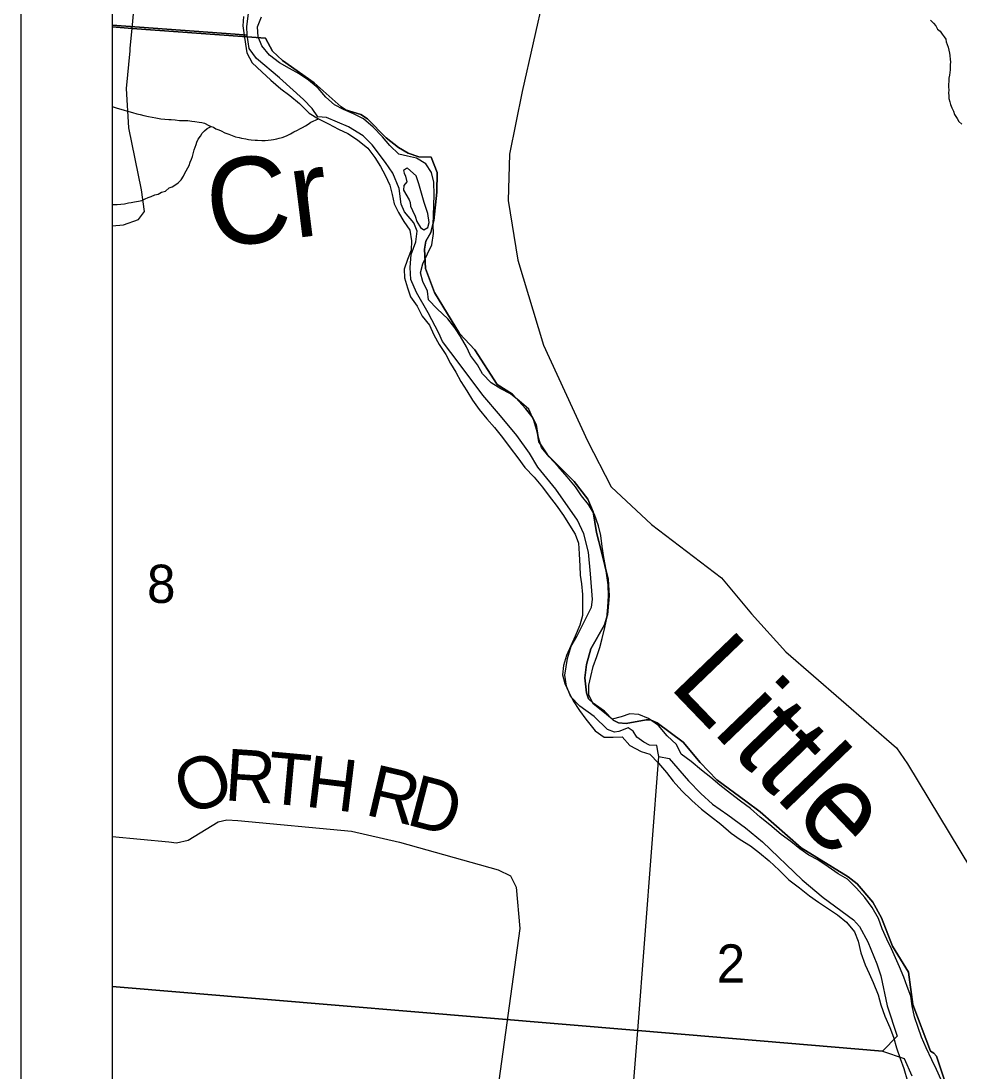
# Model space of a CAD drawing. Extents: x 0.4 to 34.4, y -2.1 to 19.9.
# Drawn here: x 2.9 to 3.928, y 16.79 to 17.94 of the extents above; entities that cross this region are included whole.
import ezdxf

# ---------------------------------------------------------------- set-up
doc = ezdxf.new("R2010")
doc.units = 0
for name, color, linetype in [('GM_X_County', 7, 'Continuous'), ('GM_X_County_Road', 7, 'Continuous'), ('GM_X_Major_River', 7, 'Continuous'), ('GM_X_Major_River_Text', 7, 'Continuous'), ('GM_X_Minor_River', 7, 'Continuous'), ('GM_X_Minor_River_Text', 7, 'Continuous'), ('GM_X_Section', 7, 'Continuous'), ('GM_X_Section_Text', 7, 'Continuous'), ('GM_X_Township', 7, 'Continuous'), ('GM_X_Township_Road', 7, 'Continuous'), ('GM_X_Township_Road_Text', 7, 'Continuous'), ('SH_Data', 7, 'Continuous')]:
    doc.layers.add(name, color=color, linetype=linetype)

msp = doc.modelspace()

# ---------------------------------------------------------------- linework, layer by layer
at = {"layer": 'GM_X_County'}
msp.add_lwpolyline([(9.8001, 15.3423), (9.8001, 18.8357), (3.0001, 18.8357), (3.0001, 12.0357), (9.5074, 12.0357)], dxfattribs=at)
at = {"layer": 'GM_X_County_Road'}
msp.add_lwpolyline([(3.497, 18.0767), (3.4489, 17.8633), (3.4351, 17.7944), (3.4337, 17.7439), (3.4443, 17.6785), (3.4724, 17.5852), (3.5204, 17.4806), (3.5463, 17.4302), (3.5906, 17.3891), (3.6672, 17.3305), (3.7001, 17.291), (3.7375, 17.2495), (3.8587, 17.1441), (3.871, 17.1268), (3.9398, 17.0125), (3.9755, 16.9529), (3.9928, 16.9155), (3.999, 16.8657), (3.9982, 16.7985), (4.0079, 16.7195)], dxfattribs=at)
at = {"layer": 'GM_X_Major_River'}
for points in [[(3.1437, 17.9452), (3.1432, 17.935), (3.1445, 17.9251), (3.1459, 17.9149), (3.1473, 17.9054), (3.1532, 17.8946), (3.164, 17.8846), (3.1737, 17.8757), (3.1846, 17.8661), (3.1944, 17.8587), (3.2052, 17.8499), (3.2157, 17.8394), (3.2258, 17.8332), (3.2368, 17.8277), (3.2477, 17.8219), (3.2579, 17.8172), (3.2687, 17.8102), (3.28, 17.8013), (3.2874, 17.7909), (3.2937, 17.781), (3.2989, 17.7714), (3.304, 17.7607), (3.3065, 17.7504), (3.3087, 17.7402), (3.3134, 17.7306), (3.3194, 17.721), (3.326, 17.7115), (3.3278, 17.6997), (3.3272, 17.6895), (3.3233, 17.6793), (3.3197, 17.6687), (3.3199, 17.6592), (3.3235, 17.6482), (3.3268, 17.6383), (3.3339, 17.6279), (3.3394, 17.6172), (3.3476, 17.6072), (3.3523, 17.5965), (3.3579, 17.5862), (3.3653, 17.5751), (3.3705, 17.5652), (3.3764, 17.5556), (3.3819, 17.5456), (3.3882, 17.5353), (3.3945, 17.525), (3.4019, 17.515), (3.4101, 17.5046), (3.4187, 17.495), (3.4273, 17.4843), (3.4358, 17.4728), (3.444, 17.462), (3.4518, 17.4513), (3.4619, 17.4409), (3.4712, 17.4297), (3.4786, 17.4201), (3.4861, 17.4102), (3.4943, 17.3987), (3.5009, 17.3883), (3.5068, 17.3784), (3.5105, 17.3685), (3.5114, 17.3567), (3.512, 17.3434), (3.5126, 17.3335), (3.514, 17.324), (3.5149, 17.3123), (3.5151, 17.3013), (3.5149, 17.2891), (3.5121, 17.2786), (3.507, 17.2665), (3.5023, 17.256), (3.4976, 17.2454), (3.494, 17.2345), (3.4931, 17.2243), (3.4956, 17.2147), (3.5, 17.2052), (3.5048, 17.1956), (3.5118, 17.1853), (3.5185, 17.1757), (3.5289, 17.163), (3.5387, 17.156), (3.5486, 17.1559), (3.5584, 17.1565), (3.567, 17.1469), (3.5791, 17.1402), (3.5889, 17.1374), (3.5982, 17.1274), (3.6068, 17.1174), (3.6142, 17.1078), (3.6236, 17.0971), (3.6348, 17.0867), (3.6453, 17.077), (3.655, 17.0693), (3.6663, 17.0608), (3.6779, 17.0507), (3.6876, 17.0438), (3.6989, 17.0371), (3.7087, 17.0294), (3.7195, 17.0205), (3.7304, 17.0101), (3.7408, 16.9997), (3.7525, 16.9908)], [(3.5418, 17.3331), (3.5401, 17.3433), (3.5383, 17.3529), (3.5366, 17.365), (3.5349, 17.3768), (3.5324, 17.3875), (3.5281, 17.3997), (3.5214, 17.4108), (3.514, 17.4204), (3.5073, 17.4303), (3.4983, 17.4411), (3.4883, 17.4526), (3.4786, 17.463), (3.47, 17.4734), (3.4671, 17.4833), (3.4646, 17.4928), (3.4617, 17.5027), (3.4562, 17.5153), (3.4457, 17.5242), (3.436, 17.5319), (3.4254, 17.5374), (3.4149, 17.544), (3.4056, 17.554), (3.4, 17.5639), (3.3922, 17.5739), (3.3878, 17.5835), (3.3815, 17.5949), (3.3752, 17.6045), (3.3674, 17.6141), (3.3558, 17.6253), (3.3465, 17.6349), (3.3451, 17.6444), (3.3403, 17.6551), (3.3375, 17.6646), (3.3403, 17.6745), (3.3454, 17.6854), (3.3501, 17.6952), (3.3518, 17.7076), (3.3516, 17.7171), (3.3517, 17.7277), (3.3523, 17.7387), (3.3525, 17.7501), (3.3523, 17.7638), (3.3498, 17.7744), (3.3435, 17.784), (3.3333, 17.7902), (3.3235, 17.7923), (3.3137, 17.7947), (3.304, 17.8039), (3.2958, 17.8136), (3.2857, 17.8243), (3.2752, 17.8332), (3.2643, 17.8387), (3.2533, 17.8434), (3.2435, 17.8485), (3.2338, 17.857), (3.2256, 17.867), (3.2151, 17.8755), (3.2046, 17.8825), (3.1941, 17.8883), (3.1831, 17.8946), (3.1723, 17.9031), (3.1637, 17.9131), (3.1597, 17.923), (3.1591, 17.934), (3.1634, 17.9449)], [(3.3235, 17.7792), (3.3222, 17.779), (3.3191, 17.7768), (3.3198, 17.7737), (3.3213, 17.7703), (3.3227, 17.7642), (3.3192, 17.7601), (3.3191, 17.7552), (3.325, 17.7445), (3.3261, 17.7418), (3.3265, 17.7376)], [(3.3265, 17.7376), (3.3287, 17.7327), (3.3316, 17.7265), (3.3334, 17.7208), (3.3375, 17.7143), (3.3412, 17.7116), (3.3458, 17.7142), (3.3471, 17.7199), (3.3457, 17.7294), (3.3417, 17.7416), (3.3388, 17.7518), (3.3356, 17.7621), (3.3327, 17.7709), (3.3235, 17.7792)], [(3.9079, 16.7806), (3.9027, 16.792), (3.8976, 16.8027), (3.8913, 16.8157), (3.8862, 16.8275), (3.8826, 16.8378), (3.8786, 16.8497), (3.8761, 16.8618), (3.8744, 16.8721), (3.8704, 16.8828), (3.8667, 16.8931), (3.8623, 16.9045), (3.8579, 16.9141), (3.8532, 16.924), (3.8484, 16.9347), (3.8433, 16.9462), (3.8392, 16.9572), (3.8322, 16.9695), (3.824, 16.9802), (3.8151, 16.9906), (3.805, 17.0006), (3.7948, 17.0064), (3.7839, 17.0138), (3.7727, 17.0216), (3.7629, 17.0267), (3.7528, 17.0336), (3.743, 17.0418), (3.7325, 17.0495), (3.7201, 17.0599), (3.7096, 17.0684), (3.6988, 17.0777), (3.6879, 17.0858), (3.677, 17.0944), (3.6654, 17.1033), (3.6557, 17.1118), (3.6452, 17.1199), (3.6339, 17.1292), (3.623, 17.1373), (3.6179, 17.148), (3.6078, 17.1576), (3.5981, 17.1688), (3.5872, 17.1765), (3.5766, 17.1809), (3.5668, 17.1814), (3.5572, 17.1781), (3.5473, 17.1756), (3.5372, 17.1841), (3.5267, 17.1926), (3.5219, 17.2022), (3.5221, 17.2128), (3.5242, 17.2226), (3.5266, 17.2332), (3.5306, 17.2445), (3.5338, 17.2543), (3.5366, 17.2642), (3.5394, 17.2762), (3.5415, 17.2864), (3.5428, 17.2982), (3.5434, 17.3107), (3.5432, 17.3228), (3.5418, 17.3331)], [(3.7525, 16.9908), (3.7637, 16.9823), (3.7735, 16.9753), (3.7832, 16.9687), (3.7941, 16.9613), (3.8039, 16.9532), (3.8128, 16.9428), (3.8168, 16.9325), (3.8197, 16.9196), (3.8244, 16.9066), (3.8288, 16.8971), (3.8332, 16.8872), (3.8387, 16.8738), (3.8416, 16.8628), (3.8459, 16.8502), (3.8514, 16.8379), (3.8554, 16.8273), (3.8587, 16.8155), (3.8627, 16.804), (3.8667, 16.793), (3.871, 16.7792)]]:
    msp.add_lwpolyline(points, dxfattribs=at)
at = {"layer": 'GM_X_Minor_River'}
for points in [[(3.896, 17.9413), (3.8993, 17.9382), (3.9019, 17.9351), (3.9038, 17.9316), (3.9067, 17.9293), (3.909, 17.9262), (3.9112, 17.9231), (3.9127, 17.9204), (3.9134, 17.9177), (3.9144, 17.9147), (3.9155, 17.9116), (3.9162, 17.9086), (3.9169, 17.9051), (3.9172, 17.9025), (3.9175, 17.8983), (3.9178, 17.8956), (3.9177, 17.8926), (3.9177, 17.8895), (3.9176, 17.8869), (3.9172, 17.8842), (3.9167, 17.8812), (3.9163, 17.8777), (3.9162, 17.8743), (3.9157, 17.8713), (3.9157, 17.8679), (3.916, 17.8652), (3.9159, 17.8614), (3.9162, 17.8587), (3.9161, 17.8557), (3.9172, 17.8519), (3.9179, 17.8488), (3.9193, 17.8454), (3.9212, 17.8415), (3.9222, 17.8381), (3.9252, 17.8338), (3.927, 17.8304), (3.9304, 17.8273)], [(3.0001, 17.8468), (3.002, 17.8462), (3.0054, 17.845), (3.0096, 17.8437), (3.013, 17.8429), (3.0183, 17.8413), (3.0221, 17.8401), (3.027, 17.8389), (3.0305, 17.838), (3.0346, 17.8368), (3.0396, 17.836), (3.0437, 17.8351), (3.0479, 17.8343), (3.0532, 17.8334), (3.0578, 17.833), (3.062, 17.8325), (3.0646, 17.8325), (3.0688, 17.832), (3.0738, 17.8315), (3.0783, 17.8315), (3.0829, 17.8314), (3.0871, 17.8309), (3.0905, 17.8305), (3.0951, 17.8296), (3.0981, 17.8292), (3.1012, 17.8284), (3.1057, 17.826), (3.1083, 17.8248), (3.111, 17.824), (3.1136, 17.8224), (3.1166, 17.8212), (3.1193, 17.8201), (3.1234, 17.8181), (3.1276, 17.8165), (3.1313, 17.8149), (3.1351, 17.8137), (3.1389, 17.8129), (3.1416, 17.812), (3.1465, 17.8112), (3.1492, 17.8108), (3.1522, 17.8103), (3.1564, 17.8099), (3.1591, 17.8098), (3.164, 17.8097), (3.1674, 17.8097), (3.1709, 17.81), (3.1739, 17.8103), (3.1766, 17.8106), (3.1801, 17.8113), (3.1828, 17.8121), (3.1862, 17.8127), (3.1889, 17.8138), (3.1916, 17.8149), (3.1954, 17.8168), (3.1989, 17.819), (3.2028, 17.8208), (3.2055, 17.8223), (3.2082, 17.8238), (3.2117, 17.8256), (3.2147, 17.8274), (3.2175, 17.8297), (3.2258, 17.8332)], [(3.0001, 17.7392), (3.0012, 17.7393), (3.0054, 17.7396), (3.0096, 17.7399), (3.0134, 17.7402), (3.018, 17.7413), (3.0207, 17.7416), (3.0245, 17.7423), (3.0287, 17.743), (3.0325, 17.744), (3.036, 17.7455), (3.0395, 17.747), (3.0425, 17.7481), (3.0468, 17.7499), (3.0502, 17.7506), (3.0541, 17.7528), (3.0583, 17.7542), (3.0622, 17.7576), (3.0656, 17.7587), (3.0687, 17.7605), (3.0722, 17.7631), (3.0754, 17.7665), (3.0781, 17.7706), (3.0797, 17.7736), (3.0809, 17.7763), (3.0829, 17.7796), (3.0841, 17.7823), (3.0853, 17.7857), (3.0869, 17.7891), (3.0878, 17.7921), (3.0886, 17.7951), (3.0898, 17.7993), (3.091, 17.8023), (3.0919, 17.805), (3.0927, 17.8076), (3.0943, 17.811), (3.0966, 17.8144), (3.0986, 17.8174), (3.101, 17.82), (3.1041, 17.8226), (3.1083, 17.8248)]]:
    msp.add_lwpolyline(points, dxfattribs=at)
at = {"layer": 'GM_X_Section'}
for p, q in [((3.0001, 17.9357), (3.0001, 16.8828)), ((3.0001, 16.8828), (3.0001, 15.5924))]:
    msp.add_line(p, q, dxfattribs=at)
for points in [[(3.4665, 18.8357), (3.0001, 18.8357), (3.0001, 17.9357)], [(3.0001, 17.9357), (3.1347, 17.9262), (3.1477, 17.925), (3.1474, 17.9343), (3.1491, 17.9487)], [(3.0001, 16.8828), (3.5755, 16.8348), (3.5985, 17.1347), (3.5979, 17.1383), (3.5964, 17.1468), (3.5885, 17.1473), (3.5821, 17.1505), (3.5746, 17.1559), (3.5706, 17.1624), (3.565, 17.1663), (3.5547, 17.1623), (3.5501, 17.1613), (3.5422, 17.1644), (3.5277, 17.1787), (3.512, 17.1899), (3.5023, 17.2), (3.4976, 17.2118), (3.4955, 17.2239), (3.4985, 17.2421), (3.5025, 17.2556), (3.5088, 17.2661), (3.5249, 17.2984), (3.5261, 17.3067), (3.5236, 17.3348), (3.5217, 17.3587), (3.5164, 17.3788), (3.5095, 17.3937), (3.4858, 17.4278), (3.4662, 17.4517), (3.457, 17.467), (3.4429, 17.4865), (3.4251, 17.508), (3.4058, 17.5307), (3.3799, 17.5653), (3.3618, 17.5894), (3.3578, 17.5986), (3.346, 17.6207), (3.3332, 17.6429), (3.327, 17.6574), (3.3261, 17.6703), (3.3275, 17.6847), (3.3326, 17.6986), (3.334, 17.7103), (3.3303, 17.7195), (3.3199, 17.7314), (3.3163, 17.7398), (3.3143, 17.7569), (3.3074, 17.7737), (3.2993, 17.7855), (3.2845, 17.8047), (3.2748, 17.8147), (3.2587, 17.8245), (3.2346, 17.8348), (3.2252, 17.8353), (3.2189, 17.8445), (3.2096, 17.8545), (3.1831, 17.8781), (3.1581, 17.8993), (3.15, 17.9104), (3.1477, 17.925), (3.1347, 17.9262), (3.0001, 17.9357)], [(3.0001, 15.5924), (3.2941, 15.5661), (3.4729, 15.5505), (3.5755, 16.8348), (3.0001, 16.8828)], [(3.4729, 15.5505), (3.5755, 16.8348), (3.8436, 16.8119), (3.8673, 16.804), (3.8757, 16.7849)]]:
    msp.add_lwpolyline(points, dxfattribs=at)
msp.add_lwpolyline([(3.5755, 16.8348), (3.5985, 17.1347), (3.6098, 17.1326), (3.631, 17.108), (3.6444, 17.0941), (3.6574, 17.0825), (3.6743, 17.0709), (3.6933, 17.0565), (3.712, 17.0414), (3.7556, 16.9998), (3.7787, 16.9804), (3.8116, 16.956), (3.8183, 16.9487), (3.8275, 16.9319), (3.8373, 16.9075), (3.8416, 16.8945), (3.8486, 16.8615), (3.8594, 16.8283), (3.8436, 16.8119)], close=True, dxfattribs=at)
at = {"layer": 'GM_X_Township'}
msp.add_line((3.0001, 17.934), (3.0001, 12.5191), dxfattribs=at)
for points in [[(6.992, 18.8357), (3.0001, 18.8357), (3.0001, 17.934)], [(3.923, 16.7452), (3.9025, 16.8065), (3.8998, 16.8099), (3.8962, 16.812), (3.8769, 16.8631), (3.8721, 16.8984), (3.8545, 16.9271), (3.8424, 16.9579), (3.833, 16.9752), (3.8158, 16.9952), (3.8059, 17.0028), (3.7543, 17.0349), (3.7096, 17.0743), (3.694, 17.0857), (3.6622, 17.1091), (3.6437, 17.1281), (3.6254, 17.1504), (3.5969, 17.1716), (3.5896, 17.1748), (3.5848, 17.1749), (3.5629, 17.1711), (3.5543, 17.1718), (3.5485, 17.1745), (3.5389, 17.1844), (3.5267, 17.1932), (3.5214, 17.1981), (3.5194, 17.2045), (3.5176, 17.2208), (3.5193, 17.2355), (3.5242, 17.2529), (3.5389, 17.279), (3.5423, 17.2901), (3.5441, 17.3106), (3.5432, 17.3289), (3.5357, 17.3589), (3.5302, 17.3803), (3.5265, 17.4028), (3.5208, 17.4165), (3.5059, 17.4361), (3.4765, 17.4654), (3.4671, 17.4793), (3.4642, 17.4986), (3.46, 17.5067), (3.4525, 17.5159), (3.4383, 17.5315), (3.4217, 17.5423), (3.3972, 17.5804), (3.3804, 17.598), (3.353, 17.6432), (3.343, 17.6695), (3.3418, 17.6905), (3.3436, 17.6991), (3.3489, 17.7089), (3.3522, 17.7219), (3.3554, 17.7528), (3.3559, 17.7744), (3.3491, 17.7912), (3.3356, 17.7915), (3.3242, 17.7955), (3.3136, 17.8017), (3.2999, 17.8124), (3.2797, 17.8334), (3.2722, 17.8379), (3.2554, 17.8432), (3.2507, 17.8463), (3.221, 17.8728), (3.1863, 17.8972), (3.1757, 17.9074), (3.1679, 17.9218), (3.0217, 17.9324), (3.0001, 17.934)], [(3.0001, 17.934), (3.0217, 17.9324), (3.1679, 17.9218), (3.1757, 17.9074), (3.1863, 17.8972), (3.221, 17.8728), (3.2507, 17.8463), (3.2554, 17.8432), (3.2722, 17.8379), (3.2797, 17.8334), (3.2999, 17.8124), (3.3136, 17.8017), (3.3242, 17.7955), (3.3356, 17.7915), (3.3491, 17.7912), (3.3559, 17.7744), (3.3554, 17.7528), (3.3522, 17.7219), (3.3489, 17.7089), (3.3436, 17.6991), (3.3418, 17.6905), (3.343, 17.6695), (3.353, 17.6432), (3.3804, 17.598), (3.3972, 17.5804), (3.4217, 17.5423), (3.4383, 17.5315), (3.4525, 17.5159), (3.46, 17.5067), (3.4642, 17.4986), (3.4671, 17.4793), (3.4765, 17.4654), (3.5059, 17.4361), (3.5208, 17.4165), (3.5265, 17.4028), (3.5302, 17.3803), (3.5357, 17.3589), (3.5432, 17.3289), (3.5441, 17.3106), (3.5423, 17.2901), (3.5389, 17.279), (3.5242, 17.2529), (3.5193, 17.2355), (3.5176, 17.2208), (3.5194, 17.2045), (3.5214, 17.1981), (3.5267, 17.1932), (3.5389, 17.1844), (3.5485, 17.1745), (3.5543, 17.1718), (3.5629, 17.1711), (3.5848, 17.1749), (3.5896, 17.1748), (3.5969, 17.1716), (3.6254, 17.1504), (3.6437, 17.1281), (3.6622, 17.1091), (3.694, 17.0857), (3.7096, 17.0743), (3.7543, 17.0349), (3.8059, 17.0028), (3.8158, 16.9952), (3.833, 16.9752), (3.8424, 16.9579), (3.8545, 16.9271), (3.8721, 16.8984), (3.8769, 16.8631), (3.8962, 16.812), (3.8998, 16.8099), (3.9025, 16.8065), (3.923, 16.7452)]]:
    msp.add_lwpolyline(points, dxfattribs=at)
at = {"layer": 'GM_X_Township_Road'}
for points in [[(3.0198, 17.9106), (3.0217, 17.9324), (3.0298, 18.0217), (3.0363, 18.1142), (3.0386, 18.1817), (3.0316, 18.2262), (3.03, 18.249), (3.0347, 18.2649), (3.0583, 18.3022), (3.0979, 18.3469)], [(3.0001, 17.7161), (3.0124, 17.7172), (3.0288, 17.723), (3.0354, 17.7317), (3.0322, 17.7556), (3.0183, 17.8233), (3.0158, 17.8666), (3.0195, 17.9076), (3.0198, 17.9106)], [(3.0001, 17.0471), (3.0621, 17.0413), (3.0705, 17.0402), (3.0832, 17.0433), (3.1159, 17.0633), (3.1254, 17.0653), (3.1374, 17.0646), (3.2622, 17.0531), (3.3145, 17.0408), (3.4225, 17.0106), (3.4361, 17.0041), (3.4423, 16.9915), (3.4463, 16.9463), (3.4191, 16.7476), (3.4117, 16.6646), (3.4129, 16.65), (3.4263, 16.6345), (3.4588, 16.6205), (3.4948, 16.6025), (3.5208, 16.5744)]]:
    msp.add_lwpolyline(points, dxfattribs=at)
at = {"layer": 'SH_Data'}
for p, q in [((2.9001, 18.9357), (2.9001, 11.9357)), ((3.0001, 18.8357), (3.0001, 12.0357))]:
    msp.add_line(p, q, dxfattribs=at)

# ---------------------------------------------------------------- texts
at = {"layer": 'GM_X_Major_River_Text'}
msp.add_text('Little', height=0.09469, rotation=313.8949, dxfattribs=at).set_placement((3.6079, 17.2121))
at = {"layer": 'GM_X_Minor_River_Text'}
msp.add_text('Cr', height=0.09469, rotation=7.0601, dxfattribs=at).set_placement((3.1088, 17.6913))
at = {"layer": 'GM_X_Section_Text'}
for s, p in [('8', (3.0381, 17.303)), ('2', (3.6619, 16.8871))]:
    msp.add_text(s, height=0.0419, rotation=0, dxfattribs=at).set_placement(p)
at = {"layer": 'GM_X_Township_Road_Text'}
for s, rotation, p in [('R', 356.18, (3.1221, 17.0869)), ('T', 354.8459, (3.1683, 17.0838)), ('O', 22.3648, (3.0826, 17.069)), ('H', 353.0986, (3.2102, 17.0801)), ('R', 346.7845, (3.2754, 17.0713)), ('D', 345.4098, (3.3205, 17.0607))]:
    msp.add_text(s, height=0.0568, rotation=rotation, dxfattribs=at).set_placement(p)

doc.saveas('drawing.dxf')
